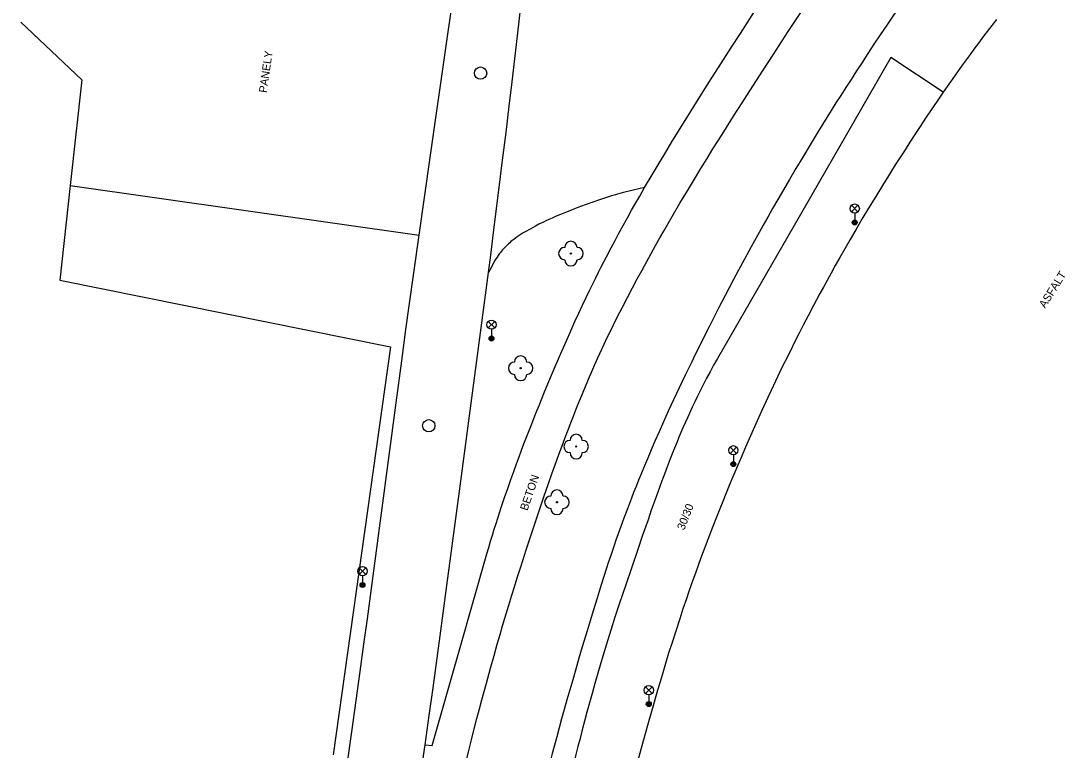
# Model space of a CAD drawing. Extents: x -541281 to -539153, y -1183881 to -1182141.
# Drawn here: x -539900.2 to -539815.4, y -1183310.7 to -1183251.4 of the extents above; entities that cross this region are included whole.
import ezdxf

# ---------------------------------------------------------------- set-up
doc = ezdxf.new("R2010")
doc.units = 0
for name, color, linetype in [('Vrstva 10', 7, 'Continuous'), ('Vrstva 11', 7, 'Continuous'), ('Vrstva 13', 7, 'Continuous'), ('Vrstva 22', 7, 'Continuous'), ('Vrstva 27', 7, 'Continuous'), ('Vrstva 33', 7, 'Continuous'), ('Vrstva 40', 7, 'Continuous'), ('Vrstva 7', 7, 'Continuous')]:
    doc.layers.add(name, color=color, linetype=linetype)

msp = doc.modelspace()

# ---------------------------------------------------------------- linework, layer by layer
at = {"layer": 'Vrstva 10'}
for p, q in [((-539859.898, -1183252.651), (-539858.404, -1183239.563)), ((-539820.984, -1183251.348), (-539821.54, -1183252.067)), ((-539860.332, -1183256.389), (-539859.898, -1183252.651)), ((-539866.978, -1183262.55), (-539865.618, -1183253.1)), ((-539827.173, -1183260.028), (-539827.598, -1183260.674)), ((-539867.88, -1183268.85), (-539866.978, -1183262.55)), ((-539832.4, -1183268.411), (-539832.863, -1183269.207)), ((-539864.492, -1183288.838), (-539862.25, -1183271.89)), ((-539871.556, -1183296.112), (-539869.749, -1183282.476)), ((-539841.728, -1183286.923), (-539842.072, -1183287.728)), ((-539865.244, -1183294.486), (-539864.492, -1183288.838)), ((-539872.078, -1183300.007), (-539871.556, -1183296.112)), ((-539845.402, -1183296.22), (-539845.738, -1183297.163))]:
    msp.add_line(p, q, dxfattribs=at)
for points in [[(-539865.618, -1183253.1), (-539864.938, -1183248.375), (-539864.26, -1183243.65)], [(-539821.54, -1183252.067), (-539822.023, -1183252.7), (-539822.443, -1183253.256), (-539822.808, -1183253.746), (-539823.125, -1183254.176), (-539823.677, -1183254.933), (-539824.088, -1183255.504), (-539824.393, -1183255.935), (-539824.849, -1183256.585), (-539825.3, -1183257.24), (-539825.796, -1183257.969), (-539826.273, -1183258.676), (-539826.732, -1183259.362), (-539827.173, -1183260.028)], [(-539861.093, -1183262.775), (-539860.819, -1183260.508), (-539860.566, -1183258.382), (-539860.332, -1183256.389)], [(-539827.598, -1183260.674), (-539828.007, -1183261.301), (-539828.4, -1183261.91), (-539828.779, -1183262.5), (-539829.143, -1183263.073), (-539829.494, -1183263.629), (-539829.832, -1183264.169), (-539830.158, -1183264.692), (-539830.783, -1183265.709), (-539831.363, -1183266.666), (-539831.901, -1183267.565), (-539832.4, -1183268.411)], [(-539862.25, -1183271.89), (-539862.063, -1183270.473), (-539861.885, -1183269.1), (-539861.715, -1183267.77), (-539861.39, -1183265.192), (-539861.093, -1183262.775)], [(-539868.684, -1183274.597), (-539868.286, -1183271.723), (-539867.88, -1183268.85)], [(-539832.863, -1183269.207), (-539833.294, -1183269.955), (-539833.694, -1183270.658), (-539834.066, -1183271.319), (-539834.412, -1183271.941), (-539834.734, -1183272.525), (-539835.034, -1183273.073), (-539835.313, -1183273.589), (-539835.832, -1183274.559), (-539836.28, -1183275.411), (-539836.669, -1183276.159), (-539837.005, -1183276.816), (-539837.298, -1183277.392), (-539837.551, -1183277.897)], [(-539869.749, -1183282.476), (-539869.293, -1183279.068), (-539868.946, -1183276.513), (-539868.684, -1183274.597)], [(-539837.551, -1183277.897), (-539837.992, -1183278.785), (-539838.318, -1183279.453), (-539838.561, -1183279.955), (-539838.922, -1183280.711), (-539839.28, -1183281.47), (-539839.545, -1183282.039), (-539840.053, -1183283.143), (-539840.522, -1183284.179), (-539840.956, -1183285.152), (-539841.357, -1183286.065), (-539841.728, -1183286.923)], [(-539842.072, -1183287.728), (-539842.39, -1183288.485), (-539842.685, -1183289.195), (-539842.959, -1183289.861), (-539843.213, -1183290.487), (-539843.449, -1183291.075), (-539843.668, -1183291.627), (-539844.073, -1183292.663), (-539844.422, -1183293.572), (-539844.723, -1183294.37), (-539844.983, -1183295.07), (-539845.207, -1183295.683), (-539845.402, -1183296.22)], [(-539866.174, -1183301.402), (-539865.676, -1183297.714), (-539865.244, -1183294.486)], [(-539845.738, -1183297.163), (-539845.986, -1183297.872), (-539846.17, -1183298.405), (-539846.442, -1183299.207), (-539846.71, -1183300.01)], [(-539872.99, -1183306.663), (-539872.663, -1183304.3), (-539872.359, -1183302.084), (-539872.078, -1183300.007)], [(-539846.71, -1183300.01), (-539847.035, -1183301.006), (-539847.333, -1183301.939), (-539847.607, -1183302.815), (-539847.859, -1183303.636), (-539848.092, -1183304.405), (-539848.307, -1183305.128), (-539848.506, -1183305.805), (-539848.873, -1183307.077), (-539849.189, -1183308.192), (-539849.461, -1183309.17)], [(-539867.39, -1183310.26), (-539867.058, -1183307.863), (-539866.748, -1183305.616), (-539866.174, -1183301.402)], [(-539874.497, -1183314.881), (-539874.374, -1183314.511), (-539874.271, -1183314.186), (-539874.185, -1183313.9), (-539874.114, -1183313.65), (-539874.054, -1183313.43), (-539874.004, -1183313.237), (-539873.923, -1183312.898), (-539873.867, -1183312.643), (-539873.828, -1183312.45), (-539873.776, -1183312.161), (-539873.73, -1183311.87), (-539873.345, -1183309.183), (-539872.99, -1183306.663)], [(-539849.461, -1183309.17), (-539849.697, -1183310.027), (-539850.105, -1183311.532), (-539850.408, -1183312.665), (-539850.635, -1183313.517), (-539850.973, -1183314.8), (-539851.311, -1183316.089), (-539851.565, -1183317.075), (-539851.797, -1183317.999)], [(-539868.719, -1183319.488), (-539868.305, -1183316.659), (-539868.101, -1183315.245), (-539867.9, -1183313.83), (-539867.644, -1183312.045), (-539867.516, -1183311.153), (-539867.39, -1183310.26)]]:
    msp.add_lwpolyline(points, dxfattribs=at)
at = {"layer": 'Vrstva 11'}
for p, q in [((-539829.55, -1183254.43), (-539836.6, -1183266.655)), ((-539825.3, -1183257.24), (-539829.55, -1183254.43)), ((-539845.556, -1183258.39), (-539844.807, -1183257.195)), ((-539844.481, -1183262.616), (-539844.005, -1183261.846)), ((-539896.221, -1183264.808), (-539867.88, -1183268.85)), ((-539836.6, -1183266.655), (-539843.65, -1183278.88)), ((-539855.564, -1183276.623), (-539855.226, -1183275.876)), ((-539858.045, -1183291.013), (-539857.708, -1183290.023)), ((-539864.6, -1183302.53), (-539862.37, -1183294.75)), ((-539850.602, -1183295.831), (-539851.12, -1183297.35)), ((-539861.097, -1183300.58), (-539860.917, -1183299.97)), ((-539866.83, -1183310.31), (-539864.6, -1183302.53)), ((-539867.39, -1183310.26), (-539866.83, -1183310.31))]:
    msp.add_line(p, q, dxfattribs=at)
for points in [[(-539839.117, -1183254.196), (-539837.886, -1183252.313), (-539836.65, -1183250.43), (-539836.222, -1183249.783), (-539835.804, -1183249.159), (-539835.396, -1183248.557), (-539834.998, -1183247.975), (-539834.611, -1183247.414), (-539834.233, -1183246.872)], [(-539844.807, -1183257.195), (-539844.147, -1183256.153), (-539843.568, -1183255.242), (-539842.549, -1183253.652), (-539841.781, -1183252.461), (-539840.623, -1183250.679), (-539839.46, -1183248.9)], [(-539844.005, -1183261.846), (-539843.556, -1183261.126), (-539843.134, -1183260.452), (-539842.338, -1183259.192), (-539841.637, -1183258.092), (-539841.02, -1183257.131), (-539839.935, -1183255.452), (-539839.117, -1183254.196)], [(-539850.355, -1183266.365), (-539849.96, -1183265.676), (-539849.56, -1183264.99), (-539848.955, -1183263.965), (-539848.384, -1183263.007), (-539847.844, -1183262.112), (-539847.336, -1183261.275), (-539846.857, -1183260.492), (-539846.406, -1183259.76), (-539845.556, -1183258.39)], [(-539849.392, -1183271.005), (-539849.025, -1183270.342), (-539848.666, -1183269.701), (-539848.316, -1183269.081), (-539847.975, -1183268.483), (-539847.643, -1183267.905), (-539847.319, -1183267.346), (-539846.686, -1183266.267), (-539846.087, -1183265.26), (-539845.52, -1183264.318), (-539844.985, -1183263.438), (-539844.481, -1183262.616)], [(-539849.56, -1183264.99), (-539850.476, -1183265.209), (-539851.392, -1183265.428), (-539851.583, -1183265.475), (-539851.76, -1183265.522), (-539851.926, -1183265.569), (-539852.236, -1183265.661), (-539852.506, -1183265.746), (-539852.741, -1183265.823), (-539853.151, -1183265.964), (-539854.38, -1183266.4), (-539854.693, -1183266.51), (-539854.984, -1183266.616), (-539855.257, -1183266.717), (-539855.511, -1183266.813), (-539855.984, -1183267), (-539856.396, -1183267.169), (-539856.755, -1183267.322), (-539857.067, -1183267.46), (-539857.339, -1183267.584), (-539857.576, -1183267.695), (-539857.783, -1183267.795), (-539858.144, -1183267.973), (-539858.414, -1183268.112), (-539858.616, -1183268.218), (-539858.919, -1183268.381)], [(-539850.961, -1183267.44), (-539850.616, -1183266.825), (-539850.355, -1183266.365)], [(-539855.226, -1183275.876), (-539854.905, -1183275.178), (-539854.6, -1183274.527), (-539854.311, -1183273.918), (-539854.036, -1183273.348), (-539853.776, -1183272.816), (-539853.53, -1183272.318), (-539853.297, -1183271.853), (-539853.077, -1183271.417), (-539852.66, -1183270.603), (-539852.289, -1183269.893), (-539851.961, -1183269.274), (-539851.671, -1183268.734), (-539851.414, -1183268.263), (-539850.961, -1183267.44)], [(-539858.919, -1183268.381), (-539859.22, -1183268.55), (-539859.415, -1183268.664), (-539859.595, -1183268.776), (-539859.761, -1183268.886), (-539859.915, -1183268.992), (-539860.056, -1183269.095), (-539860.186, -1183269.194), (-539860.306, -1183269.29), (-539860.416, -1183269.381), (-539860.517, -1183269.469), (-539860.611, -1183269.553), (-539860.697, -1183269.634), (-539860.854, -1183269.788), (-539860.986, -1183269.927), (-539861.098, -1183270.052), (-539861.193, -1183270.164), (-539861.274, -1183270.263), (-539861.343, -1183270.351), (-539861.458, -1183270.509), (-539861.541, -1183270.63), (-539861.601, -1183270.722), (-539861.687, -1183270.863), (-539861.768, -1183271.006), (-539862.009, -1183271.448), (-539862.25, -1183271.89)], [(-539853.844, -1183279.916), (-539853.601, -1183279.362), (-539853.384, -1183278.878), (-539853.192, -1183278.455), (-539852.851, -1183277.718), (-539852.59, -1183277.166), (-539852.391, -1183276.753), (-539852.088, -1183276.136), (-539851.78, -1183275.52), (-539851.361, -1183274.699), (-539850.95, -1183273.906), (-539850.547, -1183273.142), (-539850.154, -1183272.405), (-539849.769, -1183271.693), (-539849.392, -1183271.005)], [(-539859.36, -1183285.812), (-539858.996, -1183284.865), (-539858.672, -1183284.037), (-539858.384, -1183283.315), (-539858.13, -1183282.683), (-539857.679, -1183281.579), (-539857.337, -1183280.753), (-539856.817, -1183279.516), (-539856.29, -1183278.28), (-539855.918, -1183277.423), (-539855.564, -1183276.623)], [(-539843.65, -1183278.88), (-539843.805, -1183279.15), (-539843.955, -1183279.417), (-539844.245, -1183279.944), (-539844.52, -1183280.458), (-539844.78, -1183280.959), (-539845.027, -1183281.446), (-539845.261, -1183281.92), (-539845.483, -1183282.382), (-539845.695, -1183282.83), (-539845.896, -1183283.267), (-539846.088, -1183283.691), (-539846.27, -1183284.104), (-539846.445, -1183284.505), (-539846.612, -1183284.894), (-539846.771, -1183285.272), (-539846.923, -1183285.64), (-539847.213, -1183286.354), (-539847.48, -1183287.027), (-539847.725, -1183287.66)], [(-539854.427, -1183281.279), (-539854.119, -1183280.551), (-539853.844, -1183279.916)], [(-539857.708, -1183290.023), (-539857.389, -1183289.097), (-539857.085, -1183288.231), (-539856.797, -1183287.421), (-539856.523, -1183286.663), (-539856.263, -1183285.953), (-539856.015, -1183285.289), (-539855.78, -1183284.668), (-539855.557, -1183284.087), (-539855.344, -1183283.544), (-539855.143, -1183283.035), (-539854.952, -1183282.558), (-539854.771, -1183282.113), (-539854.427, -1183281.279)], [(-539862.37, -1183294.75), (-539862.217, -1183294.223), (-539862.066, -1183293.714), (-539861.917, -1183293.221), (-539861.771, -1183292.745), (-539861.626, -1183292.284), (-539861.484, -1183291.838), (-539861.203, -1183290.977), (-539860.934, -1183290.171), (-539860.675, -1183289.418), (-539860.428, -1183288.713), (-539860.192, -1183288.054), (-539859.968, -1183287.437), (-539859.754, -1183286.859), (-539859.552, -1183286.319), (-539859.36, -1183285.812)], [(-539847.725, -1183287.66), (-539847.951, -1183288.256), (-539848.16, -1183288.816), (-539848.353, -1183289.343), (-539848.71, -1183290.333), (-539849.018, -1183291.203), (-539849.284, -1183291.966), (-539849.745, -1183293.307), (-539850.088, -1183294.315), (-539850.602, -1183295.831)], [(-539860.917, -1183299.97), (-539860.595, -1183298.902), (-539860.35, -1183298.102), (-539860.164, -1183297.501), (-539859.879, -1183296.601), (-539859.59, -1183295.7), (-539859.17, -1183294.409), (-539858.774, -1183293.201), (-539858.399, -1183292.07), (-539858.045, -1183291.013)], [(-539851.12, -1183297.35), (-539851.298, -1183297.871), (-539851.642, -1183298.898), (-539851.968, -1183299.895), (-539852.277, -1183300.861), (-539852.57, -1183301.797), (-539852.848, -1183302.706), (-539853.112, -1183303.587), (-539853.363, -1183304.44), (-539853.602, -1183305.268), (-539853.828, -1183306.071), (-539854.044, -1183306.849)], [(-539863.622, -1183309.851), (-539863.393, -1183308.955), (-539863.177, -1183308.118), (-539862.972, -1183307.335), (-539862.779, -1183306.602), (-539862.411, -1183305.231), (-539862.083, -1183304.035), (-539861.791, -1183302.99), (-539861.532, -1183302.077), (-539861.302, -1183301.278), (-539861.097, -1183300.58)], [(-539854.044, -1183306.849), (-539854.249, -1183307.603), (-539854.445, -1183308.334), (-539854.631, -1183309.043), (-539854.808, -1183309.73), (-539854.977, -1183310.396), (-539855.139, -1183311.042), (-539855.293, -1183311.667), (-539855.44, -1183312.273), (-539855.719, -1183313.449), (-539855.973, -1183314.552), (-539856.206, -1183315.587), (-539856.418, -1183316.557)], [(-539865.79, -1183319.53), (-539865.637, -1183318.703), (-539865.498, -1183317.98), (-539865.373, -1183317.348), (-539865.261, -1183316.794), (-539865.16, -1183316.311), (-539864.978, -1183315.464), (-539864.837, -1183314.83), (-539864.729, -1183314.355), (-539864.562, -1183313.642), (-539864.39, -1183312.93), (-539864.119, -1183311.833), (-539863.863, -1183310.808), (-539863.622, -1183309.851)]]:
    msp.add_lwpolyline(points, dxfattribs=at)
at = {"layer": 'Vrstva 13'}
for p, q in [((-539838.285, -1183265.172), (-539838.737, -1183265.955)), ((-539843.008, -1183273.744), (-539843.553, -1183274.794)), ((-539847.633, -1183283.154), (-539848.023, -1183284.015))]:
    msp.add_line(p, q, dxfattribs=at)
for points in [[(-539827.642, -1183248.563), (-539827.921, -1183248.955), (-539828.337, -1183249.545), (-539828.75, -1183250.14), (-539829.327, -1183250.98), (-539829.881, -1183251.795), (-539830.414, -1183252.585), (-539830.927, -1183253.352), (-539831.42, -1183254.096), (-539831.895, -1183254.818), (-539832.352, -1183255.518), (-539832.791, -1183256.198), (-539833.215, -1183256.857)], [(-539833.215, -1183256.857), (-539833.623, -1183257.497), (-539834.016, -1183258.118), (-539834.394, -1183258.72), (-539834.759, -1183259.304), (-539835.46, -1183260.439), (-539836.11, -1183261.506), (-539836.715, -1183262.509), (-539837.277, -1183263.452), (-539837.799, -1183264.338), (-539838.285, -1183265.172)], [(-539838.737, -1183265.955), (-539839.159, -1183266.691), (-539839.551, -1183267.383), (-539839.917, -1183268.033), (-539840.258, -1183268.643), (-539840.892, -1183269.792), (-539841.442, -1183270.801), (-539841.919, -1183271.686), (-539842.334, -1183272.463), (-539842.694, -1183273.145), (-539843.008, -1183273.744)], [(-539843.553, -1183274.794), (-539843.959, -1183275.584), (-539844.262, -1183276.178), (-539844.712, -1183277.073), (-539845.16, -1183277.97), (-539845.451, -1183278.559), (-539845.731, -1183279.13), (-539845.999, -1183279.683), (-539846.258, -1183280.219), (-539846.753, -1183281.259), (-539847.211, -1183282.236), (-539847.633, -1183283.154)], [(-539848.023, -1183284.015), (-539848.384, -1183284.825), (-539848.717, -1183285.585), (-539849.026, -1183286.3), (-539849.311, -1183286.971), (-539849.575, -1183287.602), (-539849.819, -1183288.194), (-539850.045, -1183288.75), (-539850.255, -1183289.273), (-539850.449, -1183289.764), (-539850.63, -1183290.225), (-539850.963, -1183291.092), (-539851.248, -1183291.853), (-539851.494, -1183292.522), (-539851.705, -1183293.108)], [(-539851.705, -1183293.108), (-539851.887, -1183293.622), (-539852.045, -1183294.073), (-539852.315, -1183294.865), (-539852.514, -1183295.461), (-539852.661, -1183295.909), (-539852.878, -1183296.583), (-539853.09, -1183297.26), (-539853.421, -1183298.332), (-539853.739, -1183299.371), (-539854.045, -1183300.377), (-539854.338, -1183301.353), (-539854.621, -1183302.298)], [(-539854.621, -1183302.298), (-539854.891, -1183303.214), (-539855.151, -1183304.102), (-539855.401, -1183304.963), (-539855.64, -1183305.797), (-539855.869, -1183306.605), (-539856.089, -1183307.388), (-539856.3, -1183308.148), (-539856.502, -1183308.883), (-539856.696, -1183309.597), (-539856.881, -1183310.288), (-539857.058, -1183310.958), (-539857.228, -1183311.607)]]:
    msp.add_lwpolyline(points, dxfattribs=at)
at = {"layer": 'Vrstva 22'}
for centre in [(-539855.55, -1183270.35), (-539859.63, -1183279.66), (-539855.12, -1183286.02), (-539856.68, -1183290.55)]:
    msp.add_circle(centre, 0.05, dxfattribs=at)
for centre, start, end in [((-539855.55, -1183269.85), 359.99999, 179.99999), ((-539856.05, -1183270.35), 89.99999, 269.99999), ((-539855.05, -1183270.35), 269.99999, 89.99999), ((-539855.55, -1183270.85), 180, 360), ((-539859.63, -1183279.16), 359.99999, 179.99999), ((-539860.13, -1183279.66), 89.99999, 269.99999), ((-539859.13, -1183279.66), 269.99999, 89.99999), ((-539859.63, -1183280.16), 180, 360), ((-539855.62, -1183286.02), 89.99973, 269.99973), ((-539855.12, -1183285.52), 359.99973, 179.99973), ((-539854.62, -1183286.02), 269.99973, 89.99973), ((-539855.12, -1183286.52), 179.99973, 359.99973), ((-539856.68, -1183290.05), 359.99973, 179.99973), ((-539857.18, -1183290.55), 89.99973, 269.99973), ((-539856.18, -1183290.55), 269.99973, 89.99973), ((-539856.68, -1183291.05), 179.99973, 359.99973)]:
    msp.add_arc(centre, 0.5, start, end, dxfattribs=at)
at = {"layer": 'Vrstva 27'}
for centre in [(-539862.89, -1183255.69), (-539867.09, -1183284.33)]:
    msp.add_circle(centre, 0.5, dxfattribs=at)
at = {"layer": 'Vrstva 33'}
for p, q in [((-539832.755, -1183266.96), (-539832.225, -1183266.43)), ((-539832.755, -1183266.43), (-539832.225, -1183266.96)), ((-539832.49, -1183267.07), (-539832.49, -1183267.82)), ((-539862.265, -1183276.39), (-539861.735, -1183275.86)), ((-539862.265, -1183275.86), (-539861.735, -1183276.39)), ((-539862, -1183276.5), (-539862, -1183277.25)), ((-539842.615, -1183286.59), (-539842.085, -1183286.06)), ((-539842.615, -1183286.06), (-539842.085, -1183286.59)), ((-539842.35, -1183286.7), (-539842.35, -1183287.45)), ((-539872.745, -1183296.41), (-539872.215, -1183295.88)), ((-539872.745, -1183295.88), (-539872.215, -1183296.41)), ((-539872.48, -1183296.52), (-539872.48, -1183297.27)), ((-539849.485, -1183306.08), (-539848.955, -1183305.55)), ((-539849.485, -1183305.55), (-539848.955, -1183306.08)), ((-539849.22, -1183306.19), (-539849.22, -1183306.94))]:
    msp.add_line(p, q, dxfattribs=at)
for centre, radius in [((-539832.49, -1183266.695), 0.375), ((-539832.49, -1183267.82), 0.2), ((-539832.49, -1183267.82), 0.145), ((-539832.49, -1183267.82), 0.0876), ((-539862, -1183276.125), 0.375), ((-539862, -1183277.25), 0.2), ((-539862, -1183277.25), 0.145), ((-539862, -1183277.25), 0.0876), ((-539842.35, -1183286.325), 0.375), ((-539842.35, -1183287.45), 0.2), ((-539842.35, -1183287.45), 0.145), ((-539842.35, -1183287.45), 0.0876), ((-539872.48, -1183296.145), 0.375), ((-539872.48, -1183297.27), 0.2), ((-539872.48, -1183297.27), 0.145), ((-539872.48, -1183297.27), 0.0876), ((-539849.22, -1183305.815), 0.375), ((-539849.22, -1183306.94), 0.2), ((-539849.22, -1183306.94), 0.145), ((-539849.22, -1183306.94), 0.0876)]:
    msp.add_circle(centre, radius, dxfattribs=at)
at = {"layer": 'Vrstva 7'}
for p, q in [((-539900.23, -1183251.55), (-539895.29, -1183256.25)), ((-539895.29, -1183256.25), (-539896.221, -1183264.808)), ((-539896.221, -1183264.808), (-539897.06, -1183272.52)), ((-539897.06, -1183272.52), (-539870.19, -1183277.92)), ((-539870.19, -1183277.92), (-539874.87, -1183311.05))]:
    msp.add_line(p, q, dxfattribs=at)

# ---------------------------------------------------------------- texts
at = {"layer": 'Vrstva 40'}
for s, rotation, p in [('PANELY', 81.80402, (-539880.26, -1183257.324)), ('ASFALT', 57.90036, (-539817.024, -1183274.833)), ('BETON', 70.97401, (-539859.087, -1183291.279)), ('30/30', 68.72873, (-539846.347, -1183292.856))]:
    msp.add_text(s, height=0.65, rotation=rotation, dxfattribs=at).set_placement(p)

doc.saveas('drawing.dxf')
